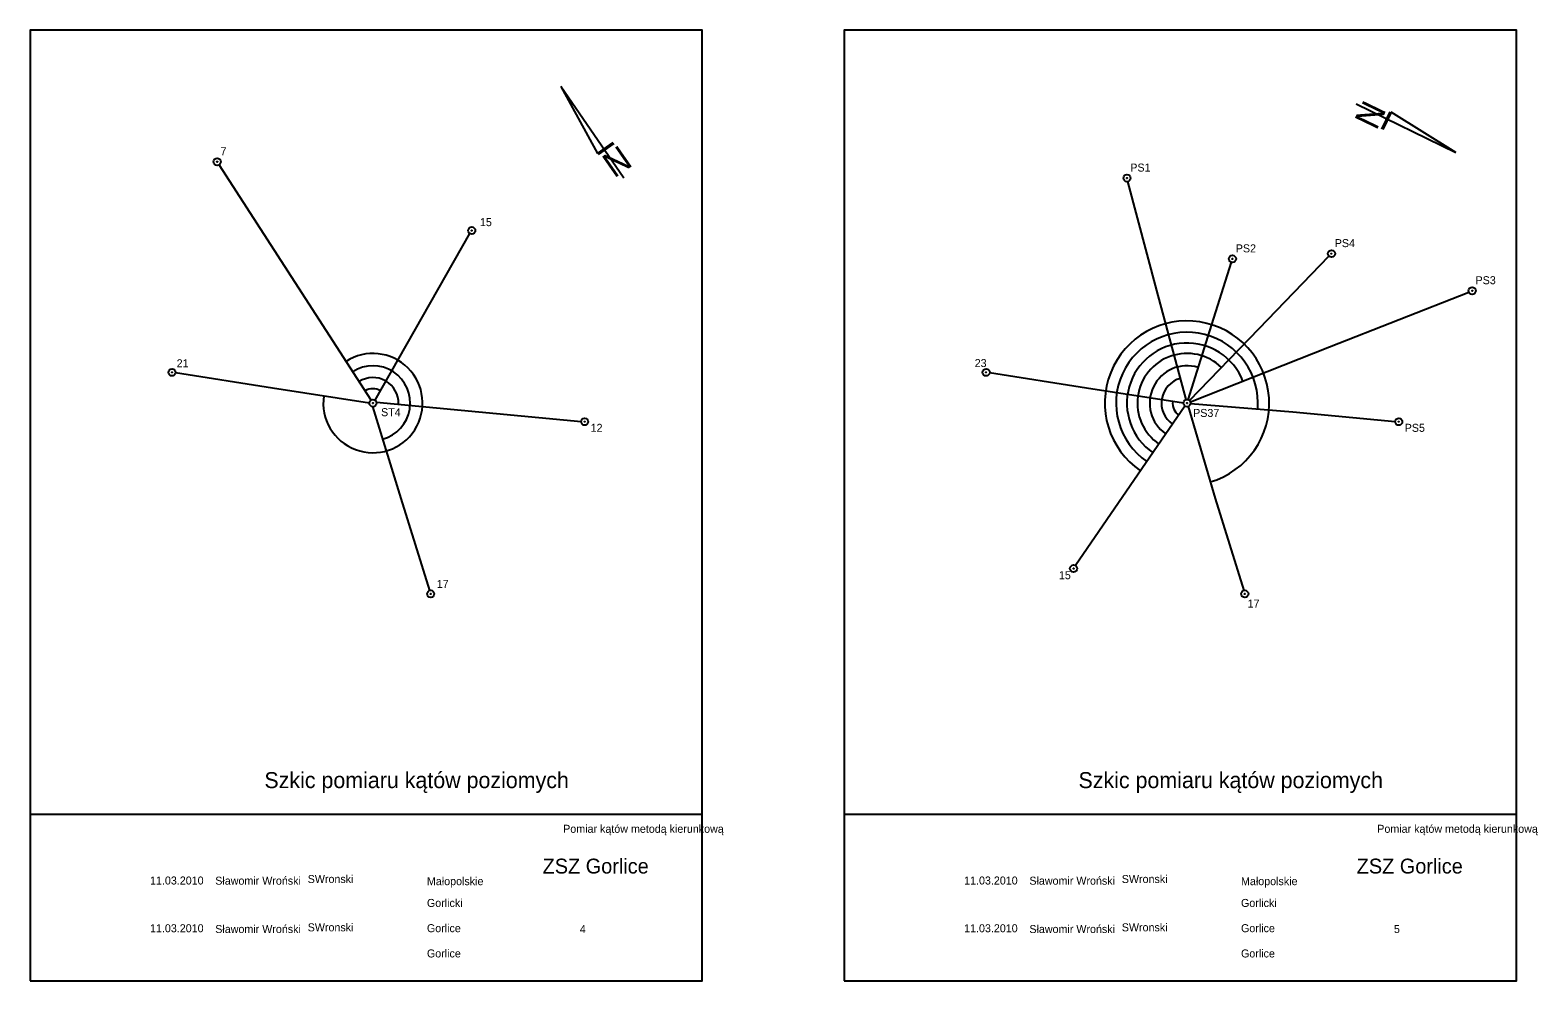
# Model space of a CAD drawing. Extents: x 4638556 to 4640059, y 5351940 to 5352237.
# Drawn here: x 4639320.6 to 4639791.7, y 5351939.6 to 5352236.6 of the extents above; entities that cross this region are included whole.
import ezdxf

# ---------------------------------------------------------------- set-up
doc = ezdxf.new("R2010")
doc.units = 0
doc.layers.add('Default', color=7, linetype='Continuous')

msp = doc.modelspace()

# ---------------------------------------------------------------- linework, layer by layer
at = {"layer": 'Default'}
for p, q in [((4639506.04, 5352190.41), (4639486.45, 5352218.99)), ((4639486.45, 5352218.99), (4639497.86, 5352198.07)), ((4639734.95, 5352213.63), (4639766.04, 5352198.34)), ((4639745.42, 5352211.11), (4639742.81, 5352205.69)), ((4639745.83, 5352210.97), (4639743.22, 5352205.54)), ((4639766.04, 5352198.34), (4639745.83, 5352210.97)), ((4639497.86, 5352198.07), (4639502.8, 5352201.51)), ((4639498.15, 5352197.74), (4639503.09, 5352201.18)), ((4639403.37, 5352157.8), (4639379.64, 5352194.55)), ((4639672.67, 5352155.25), (4639663.58, 5352189.32)), ((4639443.2, 5352147.02), (4639458.01, 5352173.04)), ((4639689.15, 5352142.63), (4639695.92, 5352164.09)), ((4639704.61, 5352143.45), (4639726.39, 5352165.99)), ((4639427.1, 5352121.04), (4639403.37, 5352157.8)), ((4639681.76, 5352121.18), (4639672.67, 5352155.25)), ((4639726.6, 5352137.65), (4639770.11, 5352154.79)), ((4639428.38, 5352120.99), (4639443.2, 5352147.02)), ((4639682.39, 5352121.17), (4639689.15, 5352142.63)), ((4639682.83, 5352120.91), (4639704.61, 5352143.45)), ((4639683.09, 5352120.51), (4639726.6, 5352137.65)), ((4639396.31, 5352124.82), (4639366.03, 5352129.53)), ((4639650.66, 5352124.82), (4639620.38, 5352129.53)), ((4639426.58, 5352120.11), (4639396.31, 5352124.82)), ((4639680.94, 5352120.11), (4639650.66, 5352124.82)), ((4639427.52, 5352119), (4639436.46, 5352090.28)), ((4639428.77, 5352120.42), (4639460.76, 5352117.4)), ((4639460.76, 5352117.4), (4639492.74, 5352114.39)), ((4639681.42, 5352119.18), (4639664.32, 5352094.26)), ((4639682.37, 5352119.03), (4639690.82, 5352090.28)), ((4639683.17, 5352120.01), (4639715.11, 5352117.4)), ((4639715.11, 5352117.4), (4639747.09, 5352114.39)), ((4639664.32, 5352094.26), (4639647.23, 5352069.34)), ((4639436.46, 5352090.28), (4639445.41, 5352061.57)), ((4639690.82, 5352090.28), (4639699.76, 5352061.57))]:
    msp.add_line(p, q, dxfattribs=at)
for points in [[(4639320.6, 5351939.61), (4639530.6, 5351939.61), (4639530.6, 5352236.61), (4639320.6, 5352236.61)], [(4639574.96, 5351939.61), (4639784.96, 5351939.61), (4639784.96, 5352236.61), (4639574.96, 5352236.61)], [(4639320.6, 5351939.61), (4639530.6, 5351939.61), (4639530.6, 5351991.61), (4639320.6, 5351991.61)], [(4639574.96, 5351939.61), (4639784.96, 5351939.61), (4639784.96, 5351991.61), (4639574.96, 5351991.61)]]:
    msp.add_lwpolyline(points, close=True, dxfattribs=at)
for centre, radius in [((4639379.03, 5352195.49), 1.12), ((4639379.03, 5352195.49), 0.0804), ((4639663.29, 5352190.39), 1.12), ((4639663.29, 5352190.39), 0.0804), ((4639458.57, 5352174.01), 1.12), ((4639458.57, 5352174.01), 0.0804), ((4639696.25, 5352165.15), 1.12), ((4639696.25, 5352165.15), 0.0804), ((4639727.17, 5352166.79), 1.12), ((4639727.17, 5352166.79), 0.0804), ((4639771.15, 5352155.2), 1.12), ((4639771.15, 5352155.2), 0.0804), ((4639364.93, 5352129.7), 1.12), ((4639619.28, 5352129.7), 1.12), ((4639364.93, 5352129.7), 0.0804), ((4639619.28, 5352129.7), 0.0804), ((4639427.7, 5352120.1), 1.12), ((4639427.7, 5352120.1), 0.0804), ((4639682.05, 5352120.1), 1.12), ((4639682.05, 5352120.1), 0.0804), ((4639493.85, 5352114.28), 1.12), ((4639493.85, 5352114.28), 0.0804), ((4639748.2, 5352114.28), 1.12), ((4639748.2, 5352114.28), 0.0804), ((4639646.6, 5352068.42), 1.12), ((4639646.6, 5352068.42), 0.0804), ((4639445.74, 5352060.5), 1.12), ((4639445.74, 5352060.5), 0.0804), ((4639700.09, 5352060.5), 1.12), ((4639700.09, 5352060.5), 0.0804)]:
    msp.add_circle(centre, radius, dxfattribs=at)
for centre, radius, start, end in [((4639682.05, 5352120.1), 25.68, 286.3749, 235.5498), ((4639682.05, 5352120.1), 22.16, 355.3282, 235.5498), ((4639427.7, 5352120.1), 15.51, 171.766, 122.8465), ((4639682.05, 5352120.1), 18.78, 21.5007, 235.5498), ((4639682.05, 5352120.1), 15.51, 45.9802, 235.5498), ((4639427.7, 5352120.1), 11.66, 284.8436, 122.8465), ((4639682.05, 5352120.1), 11.66, 72.5026, 235.5498), ((4639427.7, 5352120.1), 7.98, 357.589, 122.8465), ((4639682.05, 5352120.1), 7.98, 104.9445, 235.5498), ((4639427.7, 5352120.1), 4.51, 58.4617, 122.8465), ((4639682.05, 5352120.1), 4.51, 173.2341, 235.5498)]:
    msp.add_arc(centre, radius, start, end, dxfattribs=at)

# ---------------------------------------------------------------- texts
for rotation, p in [(244.2742, (4639737.44, 5352215.25)), (34.8809, (4639503.07, 5352190.22))]:
    msp.add_text('N', height=7.81, rotation=rotation, dxfattribs=at).set_placement(p)
for s, height, p in [('7', 2.5, (4639380.07, 5352197.53)), ('PS1', 2.5, (4639664.33, 5352192.43)), ('15', 2.5, (4639461.14, 5352175.38)), ('PS2', 2.5, (4639697.29, 5352167.19)), ('PS4', 2.5, (4639728.21, 5352168.83)), ('PS3', 2.5, (4639772.19, 5352157.24)), ('21', 2.5, (4639366.37, 5352131.3)), ('23', 2.5, (4639615.71, 5352131.36)), ('ST4', 2.5, (4639430.25, 5352116.01)), ('PS37', 2.5, (4639683.96, 5352115.78)), ('12', 2.5, (4639495.72, 5352111.13)), ('PS5', 2.5, (4639750.07, 5352111.13)), ('17', 2.5, (4639447.64, 5352062.36)), ('15', 2.5, (4639642.02, 5352065.09)), ('17', 2.5, (4639700.97, 5352056.21)), ('Szkic pomiaru kątów poziomych', 5, (4639393.79, 5351999.82)), ('Szkic pomiaru kątów poziomych', 5, (4639648.14, 5351999.82)), ('Pomiar kątów metodą kierunkową', 2.5, (4639487.14, 5351985.86)), ('Pomiar kątów metodą kierunkową', 2.5, (4639741.49, 5351985.86)), ('ZSZ Gorlice', 4.6473, (4639480.72, 5351973.14)), ('ZSZ Gorlice', 4.6473, (4639735.07, 5351973.14)), ('11.03.2010', 2.5, (4639358.06, 5351969.71)), ('Sławomir Wroński', 2.5, (4639378.44, 5351969.65)), ('SWronski', 2.5, (4639407.32, 5351970.18)), ('Małopolskie', 2.5, (4639444.57, 5351969.5)), ('11.03.2010', 2.5, (4639612.41, 5351969.71)), ('Sławomir Wroński', 2.5, (4639632.8, 5351969.65)), ('SWronski', 2.5, (4639661.67, 5351970.18)), ('Małopolskie', 2.5, (4639698.92, 5351969.5)), ('Gorlicki', 2.5, (4639444.57, 5351962.7)), ('Gorlicki', 2.5, (4639698.92, 5351962.7)), ('11.03.2010', 2.5, (4639358.06, 5351954.79)), ('Sławomir Wroński', 2.5, (4639378.44, 5351954.55)), ('SWronski', 2.5, (4639407.32, 5351955.08)), ('Gorlice', 2.5, (4639444.57, 5351954.81)), ('4', 2.5, (4639492.35, 5351954.55)), ('11.03.2010', 2.5, (4639612.41, 5351954.79)), ('Sławomir Wroński', 2.5, (4639632.8, 5351954.55)), ('SWronski', 2.5, (4639661.67, 5351955.08)), ('Gorlice', 2.5, (4639698.92, 5351954.81)), ('5', 2.5, (4639746.7, 5351954.55)), ('Gorlice', 2.5, (4639444.57, 5351946.92)), ('Gorlice', 2.5, (4639698.92, 5351946.92))]:
    msp.add_text(s, height=height, dxfattribs=at).set_placement(p)

doc.saveas('drawing.dxf')
